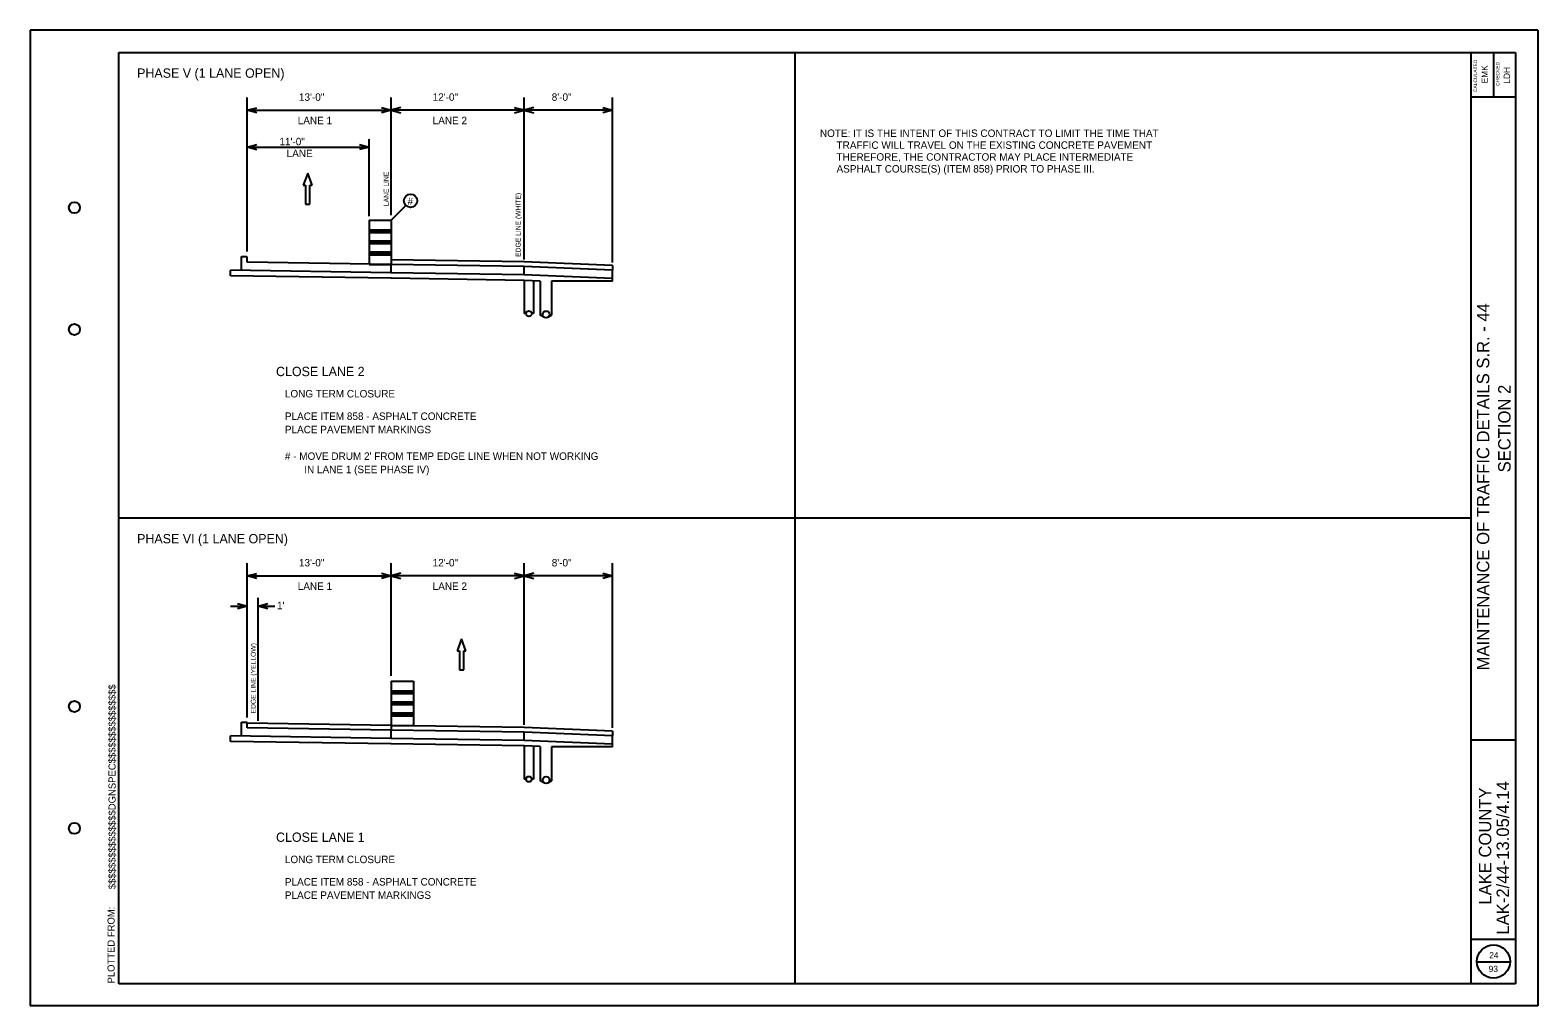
# Model space of a CAD drawing. Extents: x -161 to 291, y -369 to 173.
# Drawn here: x -160.7 to -24.7, y -369.1 to -281.1 of the extents above; entities that cross this region are included whole.
import ezdxf

# ---------------------------------------------------------------- set-up
doc = ezdxf.new("R2010")
doc.units = 0
for name, color, linetype in [('Level 1', 7, 'Continuous'), ('Level 11', 7, 'Continuous'), ('Level 21', 7, 'Continuous'), ('Level 25', 7, 'Continuous'), ('Level 26', 7, 'Continuous'), ('Level 6', 7, 'Continuous'), ('Level 7', 7, 'Continuous')]:
    doc.layers.add(name, color=color, linetype=linetype)

msp = doc.modelspace()

# ---------------------------------------------------------------- linework, layer by layer
at = {"layer": 'Level 1'}
for p, q in [((-160.72, -281.09), (-160.72, -369.08)), ((-24.74, -281.09), (-160.72, -281.09)), ((-24.74, -281.09), (-24.74, -369.08)), ((-152.73, -367.08), (-152.73, -283.09)), ((-152.73, -283.09), (-26.74, -283.09)), ((-91.73, -367.08), (-91.73, -283.09)), ((-30.74, -300.09), (-30.74, -283.09)), ((-28.74, -283.09), (-28.74, -287.09)), ((-26.74, -283.09), (-26.74, -367.08)), ((-30.74, -287.09), (-26.74, -287.09)), ((-30.74, -345.08), (-30.74, -300.09)), ((-152.73, -325.08), (-30.74, -325.08)), ((-30.74, -350.08), (-30.74, -345.08)), ((-30.74, -345.08), (-26.74, -345.08)), ((-30.74, -367.08), (-30.74, -350.08)), ((-26.74, -367.08), (-152.73, -367.08)), ((-24.74, -369.08), (-160.72, -369.08))]:
    msp.add_line(p, q, dxfattribs=at)
for centre in [(-156.73, -297.09), (-156.73, -308.08), (-156.73, -342.08), (-156.73, -353.08)]:
    msp.add_circle(centre, 0.5, dxfattribs=at)
at = {"layer": 'Level 11'}
for p, q in [((-141.66, -302.75), (-141.66, -301.51)), ((-141.66, -301.51), (-141.24, -301.51)), ((-141.16, -302.01), (-141.16, -301.6)), ((-128.18, -302.96), (-142.66, -302.74)), ((-142.66, -303.24), (-142.66, -302.74)), ((-128.18, -303.46), (-142.66, -303.24)), ((-128.16, -302.21), (-141.16, -302.01)), ((-116.18, -302.4), (-128.16, -302.21)), ((-128.16, -302.96), (-128.16, -302.21)), ((-116.17, -303.15), (-128.16, -302.96)), ((-108.19, -302.73), (-116.18, -302.4)), ((-108.19, -303.48), (-116.17, -303.15)), ((-116.16, -303.15), (-116.16, -302.4)), ((-108.19, -303.73), (-108.19, -302.73)), ((-116.18, -303.65), (-128.17, -303.46)), ((-114.71, -303.71), (-116.18, -303.65)), ((-116.16, -303.65), (-116.16, -306.65)), ((-115.33, -303.68), (-115.33, -306.65)), ((-114.71, -303.71), (-114.71, -306.8)), ((-113.71, -303.71), (-113.71, -306.79)), ((-108.19, -303.73), (-113.71, -303.71)), ((-115.99, -306.65), (-116.16, -306.65)), ((-115.33, -306.65), (-115.49, -306.65)), ((-114.32, -306.99), (-114.71, -306.8)), ((-114.03, -306.98), (-113.71, -306.79)), ((-141.66, -344.75), (-141.66, -343.51)), ((-141.66, -343.51), (-141.24, -343.51)), ((-141.16, -344.01), (-141.16, -343.59)), ((-128.16, -344.21), (-141.16, -344.01)), ((-116.17, -343.97), (-128.16, -343.79)), ((-128.16, -343.79), (-128.16, -344.21)), ((-108.19, -344.31), (-116.17, -343.97)), ((-128.18, -344.96), (-142.66, -344.73)), ((-142.66, -345.23), (-142.66, -344.73)), ((-128.18, -345.46), (-142.66, -345.23)), ((-116.18, -344.39), (-128.16, -344.21)), ((-128.16, -344.96), (-128.16, -344.21)), ((-116.17, -345.14), (-128.16, -344.96)), ((-108.19, -344.73), (-116.18, -344.39)), ((-108.19, -345.48), (-116.17, -345.14)), ((-116.16, -345.14), (-116.16, -344.39)), ((-108.19, -344.31), (-108.19, -344.73)), ((-108.19, -345.73), (-108.19, -344.73)), ((-116.18, -345.64), (-128.17, -345.46)), ((-114.71, -345.7), (-116.18, -345.64)), ((-116.16, -345.64), (-116.16, -348.64)), ((-115.33, -345.68), (-115.33, -348.64)), ((-114.71, -345.7), (-114.71, -348.8)), ((-113.71, -345.71), (-113.71, -348.78)), ((-108.19, -345.73), (-113.71, -345.71)), ((-115.99, -348.64), (-116.16, -348.64)), ((-115.33, -348.64), (-115.49, -348.64)), ((-114.32, -348.99), (-114.71, -348.8)), ((-114.03, -348.98), (-113.71, -348.78))]:
    msp.add_line(p, q, dxfattribs=at)
for centre, radius in [((-115.74, -306.65), 0.25), ((-114.19, -306.72), 0.304), ((-115.74, -348.64), 0.25), ((-114.19, -348.71), 0.304)]:
    msp.add_circle(centre, radius, dxfattribs=at)
for centre in [(-141.24, -301.6), (-141.24, -343.59)]:
    msp.add_arc(centre, 0.083, 0, 90, dxfattribs=at)
at = {"layer": 'Level 21'}
for p, q in [((-116.17, -301.98), (-128.16, -301.79)), ((-128.16, -301.79), (-128.16, -302.21)), ((-116.18, -302.4), (-128.16, -302.21)), ((-108.2, -302.73), (-116.19, -302.4)), ((-108.19, -302.31), (-116.17, -301.98)), ((-108.19, -302.31), (-108.19, -302.73)), ((-128.16, -343.79), (-141.16, -343.59)), ((-141.16, -344.01), (-141.16, -343.59)), ((-128.16, -344.21), (-141.16, -344.01)), ((-128.16, -343.79), (-128.16, -344.21)), ((-30.74, -363.08), (-26.74, -363.08)), ((-30.24, -365.11), (-27.24, -365.1))]:
    msp.add_line(p, q, dxfattribs=at)
msp.add_circle((-28.74, -365.08), 1.5, dxfattribs=at)
at = {"layer": 'Level 25'}
for p, q in [((-130.16, -298.21), (-130.16, -302.21)), ((-130.16, -298.21), (-128.16, -298.21)), ((-130.16, -299.09), (-128.16, -299.09)), ((-128.16, -298.21), (-128.16, -302.21)), ((-130.16, -299.21), (-128.16, -299.21)), ((-130.16, -299.34), (-128.16, -299.34)), ((-130.16, -300.09), (-128.16, -300.09)), ((-130.16, -300.21), (-128.16, -300.21)), ((-130.16, -300.34), (-128.16, -300.34)), ((-130.16, -301.09), (-128.16, -301.09)), ((-130.16, -301.21), (-128.16, -301.21)), ((-130.16, -301.34), (-128.16, -301.34)), ((-130.16, -302.21), (-128.16, -302.21)), ((-128.16, -339.79), (-128.16, -343.79)), ((-128.16, -339.79), (-126.16, -339.79)), ((-126.16, -339.79), (-126.16, -343.79)), ((-128.16, -340.66), (-126.16, -340.66)), ((-128.16, -340.79), (-126.16, -340.79)), ((-128.16, -340.91), (-126.16, -340.91)), ((-128.16, -341.66), (-126.16, -341.66)), ((-128.16, -341.79), (-126.16, -341.79)), ((-128.16, -341.91), (-126.16, -341.91)), ((-128.16, -342.66), (-126.16, -342.66)), ((-128.16, -342.79), (-126.16, -342.79)), ((-128.16, -342.91), (-126.16, -342.91)), ((-128.16, -343.79), (-126.16, -343.79))]:
    msp.add_line(p, q, dxfattribs=at)
at = {"layer": 'Level 26'}
for p, q in [((-141.16, -301.04), (-141.16, -287.15)), ((-128.16, -297.78), (-128.16, -287.15)), ((-116.16, -301.76), (-116.16, -287.15)), ((-108.19, -302.03), (-108.19, -287.15)), ((-141.16, -288.31), (-128.16, -288.31)), ((-116.16, -288.31), (-128.16, -288.31)), ((-108.19, -288.31), (-116.16, -288.31)), ((-130.16, -297.87), (-130.16, -290.92)), ((-141.16, -291.63), (-130.16, -291.63)), ((-128.16, -298.21), (-126.83, -296.89)), ((-141.16, -343.06), (-141.16, -329.15)), ((-141.16, -330.31), (-128.16, -330.31)), ((-128.16, -339.31), (-128.16, -329.15)), ((-116.16, -330.31), (-128.16, -330.31)), ((-116.16, -343.75), (-116.16, -329.15)), ((-108.19, -330.31), (-116.16, -330.31)), ((-108.19, -344.02), (-108.19, -329.15)), ((-142.66, -333.04), (-141.16, -333.04)), ((-140.16, -343.38), (-140.16, -332.28)), ((-140.16, -333.04), (-138.66, -333.04))]:
    msp.add_line(p, q, dxfattribs=at)
for points in [[(-140.29, -288.55), (-141.16, -288.31), (-140.29, -288.08)], [(-129.03, -288.07), (-128.16, -288.31), (-129.03, -288.54)], [(-127.29, -288.07), (-128.16, -288.31), (-127.29, -288.54)], [(-117.03, -288.55), (-116.16, -288.31), (-117.03, -288.08)], [(-115.29, -288.07), (-116.16, -288.31), (-115.29, -288.54)], [(-109.06, -288.07), (-108.19, -288.31), (-109.06, -288.54)], [(-140.29, -291.87), (-141.16, -291.63), (-140.29, -291.4)], [(-131.03, -291.39), (-130.16, -291.63), (-131.03, -291.86)], [(-140.29, -330.55), (-141.16, -330.31), (-140.29, -330.08)], [(-129.03, -330.07), (-128.16, -330.31), (-129.03, -330.54)], [(-127.29, -330.07), (-128.16, -330.31), (-127.29, -330.54)], [(-117.03, -330.55), (-116.16, -330.31), (-117.03, -330.08)], [(-115.29, -330.07), (-116.16, -330.31), (-115.29, -330.54)], [(-109.06, -330.07), (-108.19, -330.31), (-109.06, -330.54)], [(-142.03, -332.8), (-141.16, -333.04), (-142.03, -333.27)], [(-139.29, -333.28), (-140.16, -333.04), (-139.29, -332.8)]]:
    msp.add_lwpolyline(points, dxfattribs=at)
msp.add_circle((-126.41, -296.47), 0.597, dxfattribs=at)
at = {"layer": 'Level 7'}
for p, q in [((-135.69, -293.99), (-136.09, -295.06)), ((-136.09, -295.06), (-135.89, -295.06)), ((-135.89, -295.06), (-135.89, -296.79)), ((-135.29, -295.06), (-135.69, -293.99)), ((-135.5, -296.79), (-135.5, -295.06)), ((-135.5, -295.06), (-135.29, -295.06)), ((-135.89, -296.79), (-135.5, -296.79)), ((-121.82, -335.99), (-122.22, -337.06)), ((-122.22, -337.06), (-122.01, -337.06)), ((-122.01, -337.06), (-122.01, -338.78)), ((-121.42, -337.06), (-121.82, -335.99)), ((-121.62, -338.78), (-121.62, -337.06)), ((-121.62, -337.06), (-121.42, -337.06)), ((-122.01, -338.78), (-121.62, -338.78))]:
    msp.add_line(p, q, dxfattribs=at)

# ---------------------------------------------------------------- texts
at = {"layer": 'Level 1'}
for s, height, p in [('CALCULATED', 0.32, (-30.22, -286.67)), ('CHECKED', 0.32, (-28.2, -286.12)), ('EMK', 0.56, (-29.26, -285.88)), ('LDH', 0.56, (-27.26, -285.91)), ('MAINTENANCE OF TRAFFIC DETAILS S.R. - 44', 1.1199, (-29.12, -338.82)), ('SECTION 2', 1.12, (-27.2, -320.97)), ('$$$$$$$$$$$$$$$DGNSPEC$$$$$$$$$$$$$$$', 0.6386, (-153.02, -358.56)), ('LAKE COUNTY', 1.1199, (-28.94, -359.95)), ('LAK-2/44-13.05/4.14', 1.1199, (-27.34, -362.65)), ('PLOTTED FROM:', 0.6386, (-153.11, -367.06))]:
    msp.add_text(s, height=height, rotation=90, dxfattribs=at).set_placement(p)
for s, p in [('24', (-29.12, -364.79)), ('93', (-29.17, -366.03))]:
    msp.add_text(s, height=0.56, dxfattribs=at).set_placement(p)
at = {"layer": 'Level 26'}
for s, p in [('13\'-0"', (-136.48, -287.46)), ('12\'-0"', (-124.42, -287.46)), ('8\'-0"', (-113.68, -287.46)), ('LANE 1', (-136.59, -289.57)), ('LANE 2', (-124.42, -289.57)), ('11\'-0"', (-138.24, -291.47)), ('LANE', (-137.59, -292.54)), ('#', (-126.69, -296.87)), ('13\'-0"', (-136.48, -329.45)), ('12\'-0"', (-124.42, -329.45)), ('8\'-0"', (-113.68, -329.45)), ('LANE 1', (-136.59, -331.57)), ('LANE 2', (-124.42, -331.57)), ("1'", (-138.46, -333.31))]:
    msp.add_text(s, height=0.672, dxfattribs=at).set_placement(p)
for s, p in [('LANE LINE ', (-128.39, -296.96)), ('EDGE LINE (WHITE) ', (-116.49, -301.53)), ('EDGE LINE (YELLOW) ', (-140.38, -342.71))]:
    msp.add_text(s, height=0.44, rotation=90, dxfattribs=at).set_placement(p)
at = {"layer": 'Level 6'}
for s, height, p in [('PHASE V (1 LANE OPEN)', 0.84, (-151.08, -285.38)), ('NOTE: IT IS THE INTENT OF THIS CONTRACT TO LIMIT THE TIME THAT', 0.672, (-89.49, -290.72)), ('      TRAFFIC WILL TRAVEL ON THE EXISTING CONCRETE PAVEMENT', 0.672, (-89.49, -291.79)), ('      THEREFORE, THE CONTRACTOR MAY PLACE INTERMEDIATE ', 0.672, (-89.49, -292.86)), ('      ASPHALT COURSE(S) (ITEM 858) PRIOR TO PHASE III. ', 0.672, (-89.49, -293.93)), ('CLOSE LANE 2', 0.84, (-138.55, -312.29)), ('LONG TERM CLOSURE', 0.672, (-137.75, -314.21)), ('PLACE ITEM 858 - ASPHALT CONCRETE', 0.672, (-137.75, -316.24)), ('PLACE PAVEMENT MARKINGS', 0.672, (-137.75, -317.44)), ("# - MOVE DRUM 2' FROM TEMP EDGE LINE WHEN NOT WORKING", 0.672, (-137.75, -319.84)), ('       IN LANE 1 (SEE PHASE IV)', 0.672, (-137.75, -321.04)), ('PHASE VI (1 LANE OPEN)', 0.84, (-151.08, -327.37)), ('CLOSE LANE 1', 0.84, (-138.55, -354.29)), ('LONG TERM CLOSURE', 0.672, (-137.75, -356.21)), ('PLACE ITEM 858 - ASPHALT CONCRETE', 0.672, (-137.75, -358.23)), ('PLACE PAVEMENT MARKINGS', 0.672, (-137.75, -359.43))]:
    msp.add_text(s, height=height, dxfattribs=at).set_placement(p)

doc.saveas('drawing.dxf')
